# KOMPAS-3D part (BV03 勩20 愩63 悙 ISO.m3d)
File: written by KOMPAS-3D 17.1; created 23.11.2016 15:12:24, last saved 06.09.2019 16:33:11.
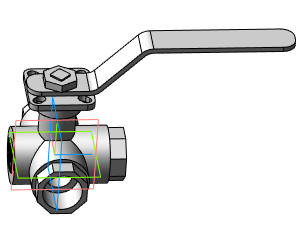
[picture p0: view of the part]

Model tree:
1. Операция без истории:1  (labels: Сталь 20  ГОСТ 1050-88)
